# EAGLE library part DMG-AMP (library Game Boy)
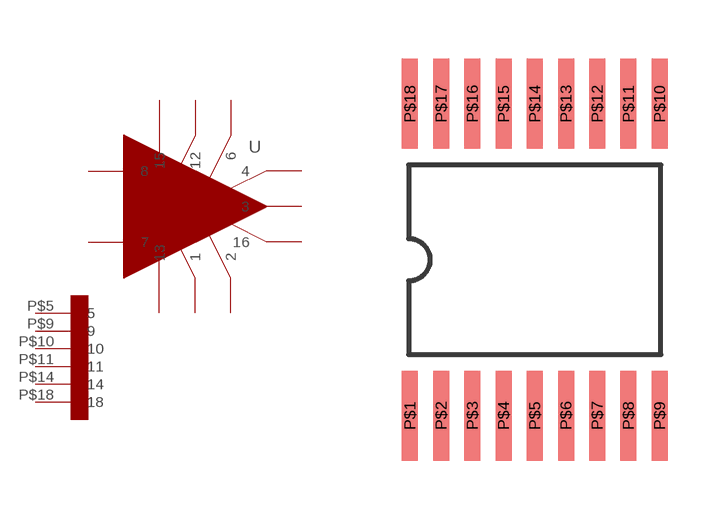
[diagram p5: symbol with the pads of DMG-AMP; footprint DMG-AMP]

Designator prefix -

## DMG-AMP  [DMG-AMP]
P$1  1
P$2  2
P$3  3
P$4  4
P$5  5
P$6  6
P$7  7
P$8  8
P$9  9
P$10  10
P$11  11
P$12  12
P$13  13
P$14  14
P$15  15
P$16  16
P$18  18

## Footprint DMG-AMP (pad centres in mm)
smd 0.406 x 2.286: P$1 -3.175,-3.969; P$2 -2.381,-3.969; P$3 -1.587,-3.969; P$4 -0.794,-3.969; P$5 0,-3.969; P$6 0.794,-3.969; P$7 1.587,-3.969; P$8 2.381,-3.969; P$9 3.175,-3.969; P$10 3.175,3.969; P$11 2.381,3.969; P$12 1.587,3.969; P$13 0.794,3.969; P$14 0,3.969; P$15 -0.794,3.969; P$16 -1.587,3.969; P$17 -2.381,3.969; P$18 -3.175,3.969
